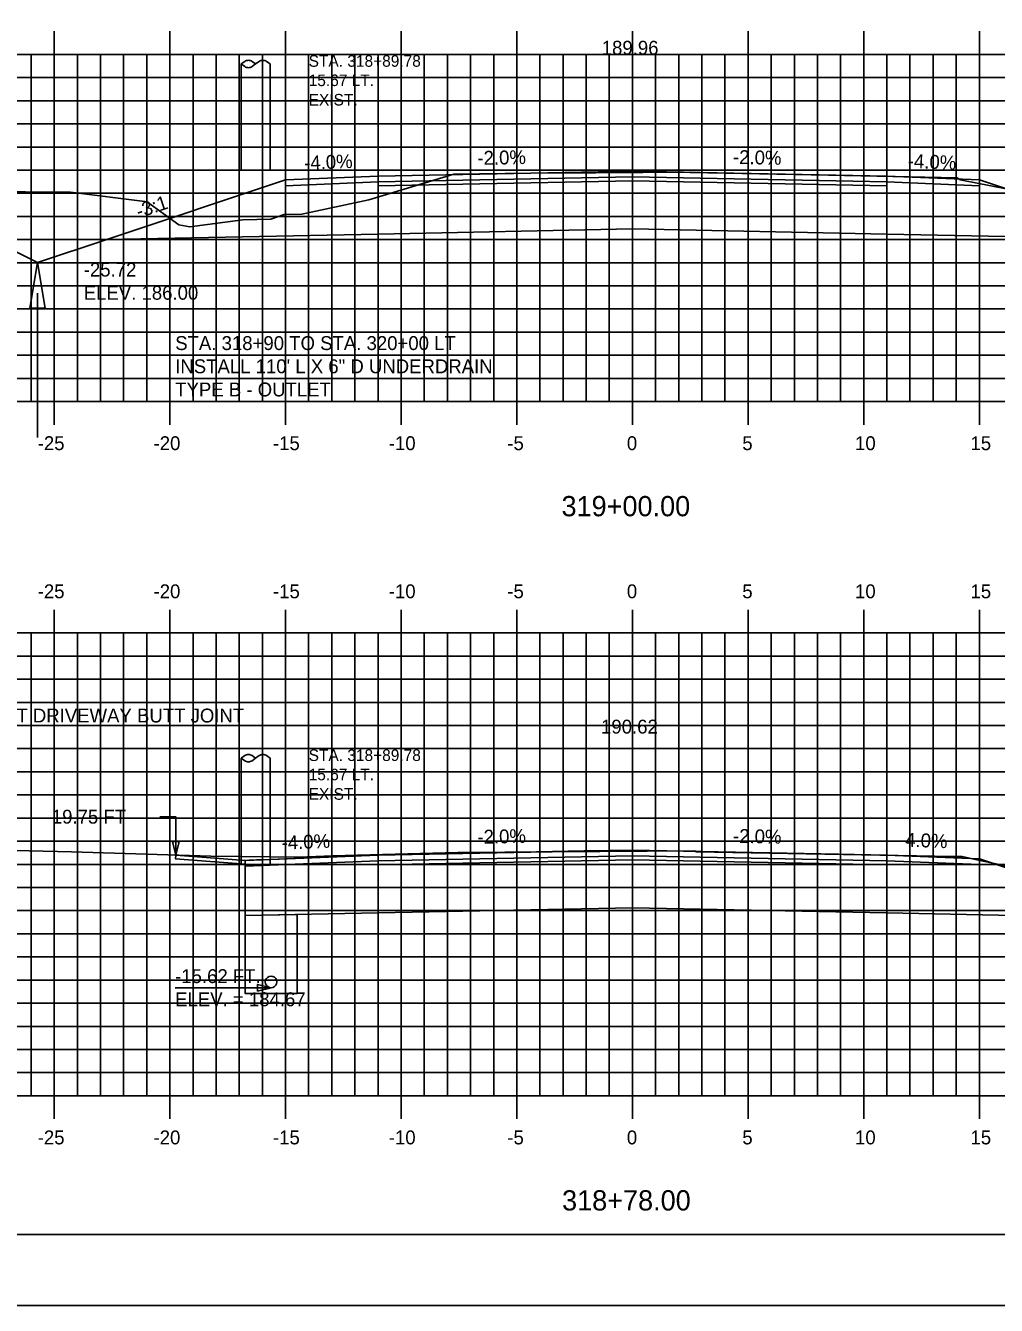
# Model space of a CAD drawing. Extents: x 1139428 to 1139598, y 608981 to 609091.
# Drawn here: x 1139485.2 to 1139527.2, y 608981.3 to 609036.6 of the extents above; entities that cross this region are included whole.
import ezdxf

# ---------------------------------------------------------------- set-up
doc = ezdxf.new("R2010")
doc.units = 0
for name, color, linetype in [('ANNOTATION', 7, 'Continuous'), ('BORDER', 7, 'Continuous'), ('D_Drainage_Ditch_Line', 7, 'Continuous'), ('D_Drainage_Underdrain', 7, 'Continuous'), ('D_Drainage_Underdrain_06in', 7, 'Continuous'), ('D_Roadway_Centerline', 7, 'Continuous'), ('D_Roadway_Centerline_Text', 7, 'Continuous'), ('D_Roadway_Edge_Shoulder', 7, 'Continuous'), ('D_Roadway_Edge_TW', 7, 'Continuous'), ('D_Roadway_Pavement', 7, 'Continuous'), ('D_Roadway_SlopeLines', 7, 'Continuous'), ('D_Roadway_SubGrade', 7, 'Continuous'), ('D_Text_Monospaced', 7, 'Continuous'), ('D_Text_Standard', 7, 'Continuous'), ('H_V ANNOTATION', 7, 'Continuous'), ('MAJOR', 7, 'Continuous'), ('MINOR', 7, 'Continuous'), ('PLOT BOUNDARY', 7, 'Continuous'), ('S_Roadway_Centerline', 7, 'Continuous'), ('S_Utilities_Pole_Stub', 7, 'Continuous')]:
    doc.layers.add(name, color=color, linetype=linetype)

msp = doc.modelspace()

# ---------------------------------------------------------------- linework, layer by layer
for points in [[(1139477.03, 609029.476), (1139478.28, 609029.383), (1139479.53, 609029.138), (1139480.78, 609028.741), (1139482.03, 609028.192), (1139485.737, 609026.338), (1139488.737, 609027.338), (1139496.461, 609029.913), (1139496.462, 609029.913), (1139500.462, 609030.073), (1139511.462, 609030.293), (1139522.462, 609030.073), (1139526.462, 609029.913), (1139534.185, 609027.338), (1139537.185, 609026.338), (1139537.772, 609026.632), (1139539.022, 609027.171), (1139540.272, 609027.537), (1139541.522, 609027.732), (1139542.772, 609027.754)], [(1139494.711, 609000.505), (1139494.712, 609000.505), (1139494.712, 609000.505), (1139494.878, 609000.511), (1139494.916, 609000.513), (1139494.972, 609000.515), (1139495.212, 609000.525), (1139495.414, 609000.533), (1139495.462, 609000.535), (1139499.514, 609000.697), (1139500.462, 609000.735), (1139509.376, 609000.913), (1139511.462, 609000.955), (1139520.376, 609000.776), (1139522.462, 609000.735), (1139525.703, 609000.605), (1139526.462, 609000.575), (1139532.721, 608998.488)]]:
    msp.add_lwpolyline(points)
at = {"layer": 'BORDER'}
msp.add_lwpolyline([(1139436.462, 608984.335), (1139596.462, 608984.335), (1139596.462, 609089.335), (1139436.462, 609089.335)], close=True, dxfattribs=at)
at = {"layer": 'D_Drainage_Ditch_Line'}
msp.add_line((1139485.737, 609025.026), (1139485.737, 609018.783), dxfattribs=at)
msp.add_lwpolyline([(1139486.065, 609024.37), (1139485.409, 609024.37), (1139485.737, 609026.338)], close=True, dxfattribs=at)
at = {"layer": 'D_Drainage_Underdrain'}
msp.add_lwpolyline([(1139494.712, 608998.12), (1139494.712, 608994.755), (1139496.962, 608994.755), (1139496.962, 608998.165)], close=True, dxfattribs=at)
at = {"layer": 'D_Drainage_Underdrain_06in'}
msp.add_lwpolyline([(1139495.837, 608995.505), (1139495.915, 608995.492), (1139495.984, 608995.457), (1139496.04, 608995.402), (1139496.075, 608995.332), (1139496.087, 608995.255), (1139496.075, 608995.177), (1139496.04, 608995.108), (1139495.984, 608995.052), (1139495.915, 608995.017), (1139495.837, 608995.005), (1139495.76, 608995.017), (1139495.69, 608995.052), (1139495.635, 608995.108), (1139495.6, 608995.177), (1139495.587, 608995.255), (1139495.6, 608995.332), (1139495.635, 608995.402), (1139495.69, 608995.457), (1139495.76, 608995.492)], close=True, dxfattribs=at)
at = {"layer": 'D_Roadway_Edge_Shoulder'}
for points in [[(1139500.462, 609030.073), (1139496.462, 609029.913), (1139496.462, 609029.663), (1139500.462, 609029.823)], [(1139522.462, 609030.073), (1139526.462, 609029.913), (1139526.462, 609029.663), (1139522.462, 609029.823)], [(1139494.712, 609000.505), (1139491.716, 609000.734), (1139491.708, 609000.568), (1139494.711, 609000.338)], [(1139522.462, 609000.735), (1139526.462, 609000.575), (1139526.462, 609000.325), (1139522.462, 609000.485)]]:
    msp.add_lwpolyline(points, close=True, dxfattribs=at)
msp.add_lwpolyline([(1139500.462, 609000.735), (1139495.462, 609000.535), (1139494.712, 609000.505), (1139494.712, 609000.255), (1139500.462, 609000.485), (1139500.462, 609000.735)], dxfattribs=at)
at = {"layer": 'D_Roadway_Edge_TW'}
for points in [[(1139500.462, 609029.823), (1139500.462, 609030.073), (1139511.462, 609030.293), (1139522.462, 609030.073), (1139522.462, 609029.823), (1139511.462, 609030.043)], [(1139500.462, 609000.485), (1139500.462, 609000.735), (1139511.462, 609000.955), (1139522.462, 609000.735), (1139522.462, 609000.485), (1139511.462, 609000.705)]]:
    msp.add_lwpolyline(points, close=True, dxfattribs=at)
at = {"layer": 'D_Roadway_Pavement'}
for points in [[(1139500.462, 609029.656), (1139500.462, 609029.823), (1139511.462, 609030.043), (1139522.462, 609029.823), (1139522.462, 609029.656), (1139511.462, 609029.876)], [(1139500.462, 609000.318), (1139500.462, 609000.485), (1139511.462, 609000.705), (1139522.462, 609000.485), (1139522.462, 609000.318), (1139511.462, 609000.538)]]:
    msp.add_lwpolyline(points, close=True, dxfattribs=at)
at = {"layer": 'D_Roadway_SlopeLines'}
for points in [[(1139485.737, 609026.338), (1139482.03, 609028.192), (1139480.78, 609028.741), (1139479.53, 609029.138), (1139478.28, 609029.383), (1139477.03, 609029.476)], [(1139488.737, 609027.338), (1139485.737, 609026.338)]]:
    msp.add_lwpolyline(points, dxfattribs=at)
at = {"layer": 'D_Roadway_SubGrade'}
for points in [[(1139500.462, 609029.656), (1139500.462, 609029.823), (1139496.462, 609029.663), (1139496.462, 609029.913), (1139496.461, 609029.913), (1139488.737, 609027.338), (1139500.462, 609027.573)], [(1139500.462, 609027.573), (1139500.462, 609029.656), (1139511.462, 609029.876), (1139522.462, 609029.656), (1139522.462, 609027.573), (1139511.462, 609027.793)], [(1139522.462, 609029.656), (1139522.462, 609029.823), (1139526.462, 609029.663), (1139526.462, 609029.913), (1139526.462, 609029.913), (1139534.185, 609027.338), (1139522.462, 609027.573)], [(1139494.711, 608999.505), (1139494.712, 608998.12), (1139500.462, 608998.235), (1139500.462, 609000.318), (1139500.462, 609000.485), (1139494.712, 609000.255), (1139494.712, 609000.505), (1139494.711, 609000.505)], [(1139500.462, 609000.318), (1139500.462, 609000.485), (1139494.712, 609000.255), (1139494.712, 609000.505), (1139494.711, 609000.505), (1139494.712, 608998.12), (1139500.462, 608998.235)], [(1139500.462, 608998.235), (1139500.462, 609000.318), (1139511.462, 609000.538), (1139522.462, 609000.318), (1139522.462, 608998.235), (1139511.462, 608998.455)], [(1139522.462, 609000.318), (1139522.462, 609000.485), (1139526.462, 609000.325), (1139526.462, 609000.575), (1139526.462, 609000.575), (1139534.185, 608998), (1139522.462, 608998.235)]]:
    msp.add_lwpolyline(points, close=True, dxfattribs=at)
at = {"layer": 'D_Text_Standard'}
msp.add_line((1139491.688, 608995.005), (1139494.155, 608995.005), dxfattribs=at)
for points in [[(1139491.716, 609000.734), (1139491.712, 609002.396), (1139491.032, 609002.396)], [(1139495.837, 608995.005), (1139494.835, 608995.005), (1139494.155, 608995.005)]]:
    msp.add_lwpolyline(points, dxfattribs=at)
for points in [[(1139491.716, 609000.734), (1139491.569, 609001.316), (1139491.86, 609001.316)], [(1139495.837, 608995.005), (1139495.255, 608994.859), (1139495.255, 608995.15)]]:
    msp.add_lwpolyline(points, close=True, dxfattribs=at)
at = {"layer": 'MAJOR'}
for p, q in [((1139486.462, 609036.337), (1139486.462, 609035.335)), ((1139491.462, 609036.337), (1139491.462, 609035.335)), ((1139496.462, 609036.337), (1139496.462, 609035.335)), ((1139501.462, 609036.337), (1139501.462, 609035.335)), ((1139506.462, 609036.337), (1139506.462, 609035.335)), ((1139511.462, 609036.337), (1139511.462, 609035.335)), ((1139516.462, 609036.337), (1139516.462, 609035.335)), ((1139521.462, 609036.337), (1139521.462, 609035.335)), ((1139526.462, 609036.337), (1139526.462, 609035.335)), ((1139441.462, 609035.335), (1139581.462, 609035.335)), ((1139441.462, 609035.335), (1139581.462, 609035.335)), ((1139486.462, 609020.335), (1139486.462, 609035.335)), ((1139491.462, 609020.335), (1139491.462, 609035.335)), ((1139496.462, 609020.335), (1139496.462, 609035.335)), ((1139501.462, 609020.335), (1139501.462, 609035.335)), ((1139506.462, 609020.335), (1139506.462, 609035.335)), ((1139511.462, 609020.335), (1139511.462, 609035.335)), ((1139516.462, 609020.335), (1139516.462, 609035.335)), ((1139521.462, 609020.335), (1139521.462, 609035.335)), ((1139526.462, 609020.335), (1139526.462, 609035.335)), ((1139441.462, 609030.335), (1139581.462, 609030.335)), ((1139441.462, 609025.335), (1139581.462, 609025.335)), ((1139441.462, 609020.335), (1139581.462, 609020.335)), ((1139441.462, 609020.335), (1139581.462, 609020.335)), ((1139486.462, 609019.333), (1139486.462, 609020.335)), ((1139491.462, 609019.333), (1139491.462, 609020.335)), ((1139496.462, 609019.333), (1139496.462, 609020.335)), ((1139501.462, 609019.333), (1139501.462, 609020.335)), ((1139506.462, 609019.333), (1139506.462, 609020.335)), ((1139511.462, 609019.333), (1139511.462, 609020.335)), ((1139516.462, 609019.333), (1139516.462, 609020.335)), ((1139521.462, 609019.333), (1139521.462, 609020.335)), ((1139526.462, 609019.333), (1139526.462, 609020.335)), ((1139486.462, 609011.337), (1139486.462, 609010.335)), ((1139491.462, 609011.337), (1139491.462, 609010.335)), ((1139496.462, 609011.337), (1139496.462, 609010.335)), ((1139501.462, 609011.337), (1139501.462, 609010.335)), ((1139506.462, 609011.337), (1139506.462, 609010.335)), ((1139511.462, 609011.337), (1139511.462, 609010.335)), ((1139516.462, 609011.337), (1139516.462, 609010.335)), ((1139521.462, 609011.337), (1139521.462, 609010.335)), ((1139526.462, 609011.337), (1139526.462, 609010.335)), ((1139441.462, 609010.335), (1139581.462, 609010.335)), ((1139441.462, 609010.335), (1139581.462, 609010.335)), ((1139486.462, 608990.335), (1139486.462, 609010.335)), ((1139491.462, 608990.335), (1139491.462, 609010.335)), ((1139496.462, 608990.335), (1139496.462, 609010.335)), ((1139501.462, 608990.335), (1139501.462, 609010.335)), ((1139506.462, 608990.335), (1139506.462, 609010.335)), ((1139511.462, 608990.335), (1139511.462, 609010.335)), ((1139516.462, 608990.335), (1139516.462, 609010.335)), ((1139521.462, 608990.335), (1139521.462, 609010.335)), ((1139526.462, 608990.335), (1139526.462, 609010.335)), ((1139441.462, 609005.335), (1139581.462, 609005.335)), ((1139441.462, 609000.335), (1139581.462, 609000.335)), ((1139441.462, 608995.335), (1139581.462, 608995.335)), ((1139441.462, 608990.335), (1139581.462, 608990.335)), ((1139441.462, 608990.335), (1139581.462, 608990.335)), ((1139486.462, 608989.333), (1139486.462, 608990.335)), ((1139491.462, 608989.333), (1139491.462, 608990.335)), ((1139496.462, 608989.333), (1139496.462, 608990.335)), ((1139501.462, 608989.333), (1139501.462, 608990.335)), ((1139506.462, 608989.333), (1139506.462, 608990.335)), ((1139511.462, 608989.333), (1139511.462, 608990.335)), ((1139516.462, 608989.333), (1139516.462, 608990.335)), ((1139521.462, 608989.333), (1139521.462, 608990.335)), ((1139526.462, 608989.333), (1139526.462, 608990.335))]:
    msp.add_line(p, q, dxfattribs=at)
at = {"layer": 'MINOR'}
for p, q in [((1139485.462, 609020.335), (1139485.462, 609035.335)), ((1139487.462, 609020.335), (1139487.462, 609035.335)), ((1139488.462, 609020.335), (1139488.462, 609035.335)), ((1139489.462, 609020.335), (1139489.462, 609035.335)), ((1139490.462, 609020.335), (1139490.462, 609035.335)), ((1139492.462, 609020.335), (1139492.462, 609035.335)), ((1139493.462, 609020.335), (1139493.462, 609035.335)), ((1139494.462, 609020.335), (1139494.462, 609035.335)), ((1139495.462, 609020.335), (1139495.462, 609035.335)), ((1139497.462, 609020.335), (1139497.462, 609035.335)), ((1139498.462, 609020.335), (1139498.462, 609035.335)), ((1139499.462, 609020.335), (1139499.462, 609035.335)), ((1139500.462, 609020.335), (1139500.462, 609035.335)), ((1139502.462, 609020.335), (1139502.462, 609035.335)), ((1139503.462, 609020.335), (1139503.462, 609035.335)), ((1139504.462, 609020.335), (1139504.462, 609035.335)), ((1139505.462, 609020.335), (1139505.462, 609035.335)), ((1139507.462, 609020.335), (1139507.462, 609035.335)), ((1139508.462, 609020.335), (1139508.462, 609035.335)), ((1139509.462, 609020.335), (1139509.462, 609035.335)), ((1139510.462, 609020.335), (1139510.462, 609035.335)), ((1139512.462, 609020.335), (1139512.462, 609035.335)), ((1139513.462, 609020.335), (1139513.462, 609035.335)), ((1139514.462, 609020.335), (1139514.462, 609035.335)), ((1139515.462, 609020.335), (1139515.462, 609035.335)), ((1139517.462, 609020.335), (1139517.462, 609035.335)), ((1139518.462, 609020.335), (1139518.462, 609035.335)), ((1139519.462, 609020.335), (1139519.462, 609035.335)), ((1139520.462, 609020.335), (1139520.462, 609035.335)), ((1139522.462, 609020.335), (1139522.462, 609035.335)), ((1139523.462, 609020.335), (1139523.462, 609035.335)), ((1139524.462, 609020.335), (1139524.462, 609035.335)), ((1139525.462, 609020.335), (1139525.462, 609035.335)), ((1139441.462, 609034.335), (1139581.462, 609034.335)), ((1139441.462, 609033.335), (1139581.462, 609033.335)), ((1139441.462, 609032.335), (1139581.462, 609032.335)), ((1139441.462, 609031.335), (1139581.462, 609031.335)), ((1139441.462, 609029.335), (1139581.462, 609029.335)), ((1139441.462, 609028.335), (1139581.462, 609028.335)), ((1139441.462, 609027.335), (1139581.462, 609027.335)), ((1139441.462, 609026.335), (1139581.462, 609026.335)), ((1139441.462, 609024.335), (1139581.462, 609024.335)), ((1139441.462, 609023.335), (1139581.462, 609023.335)), ((1139441.462, 609022.335), (1139581.462, 609022.335)), ((1139441.462, 609021.335), (1139581.462, 609021.335)), ((1139485.462, 608990.335), (1139485.462, 609010.335)), ((1139487.462, 608990.335), (1139487.462, 609010.335)), ((1139488.462, 608990.335), (1139488.462, 609010.335)), ((1139489.462, 608990.335), (1139489.462, 609010.335)), ((1139490.462, 608990.335), (1139490.462, 609010.335)), ((1139492.462, 608990.335), (1139492.462, 609010.335)), ((1139493.462, 608990.335), (1139493.462, 609010.335)), ((1139494.462, 608990.335), (1139494.462, 609010.335)), ((1139495.462, 608990.335), (1139495.462, 609010.335)), ((1139497.462, 608990.335), (1139497.462, 609010.335)), ((1139498.462, 608990.335), (1139498.462, 609010.335)), ((1139499.462, 608990.335), (1139499.462, 609010.335)), ((1139500.462, 608990.335), (1139500.462, 609010.335)), ((1139502.462, 608990.335), (1139502.462, 609010.335)), ((1139503.462, 608990.335), (1139503.462, 609010.335)), ((1139504.462, 608990.335), (1139504.462, 609010.335)), ((1139505.462, 608990.335), (1139505.462, 609010.335)), ((1139507.462, 608990.335), (1139507.462, 609010.335)), ((1139508.462, 608990.335), (1139508.462, 609010.335)), ((1139509.462, 608990.335), (1139509.462, 609010.335)), ((1139510.462, 608990.335), (1139510.462, 609010.335)), ((1139512.462, 608990.335), (1139512.462, 609010.335)), ((1139513.462, 608990.335), (1139513.462, 609010.335)), ((1139514.462, 608990.335), (1139514.462, 609010.335)), ((1139515.462, 608990.335), (1139515.462, 609010.335)), ((1139517.462, 608990.335), (1139517.462, 609010.335)), ((1139518.462, 608990.335), (1139518.462, 609010.335)), ((1139519.462, 608990.335), (1139519.462, 609010.335)), ((1139520.462, 608990.335), (1139520.462, 609010.335)), ((1139522.462, 608990.335), (1139522.462, 609010.335)), ((1139523.462, 608990.335), (1139523.462, 609010.335)), ((1139524.462, 608990.335), (1139524.462, 609010.335)), ((1139525.462, 608990.335), (1139525.462, 609010.335)), ((1139441.462, 609009.335), (1139581.462, 609009.335)), ((1139441.462, 609008.335), (1139581.462, 609008.335)), ((1139441.462, 609007.335), (1139581.462, 609007.335)), ((1139441.462, 609006.335), (1139581.462, 609006.335)), ((1139441.462, 609004.335), (1139581.462, 609004.335)), ((1139441.462, 609003.335), (1139581.462, 609003.335)), ((1139441.462, 609002.335), (1139581.462, 609002.335)), ((1139441.462, 609001.335), (1139581.462, 609001.335)), ((1139441.462, 608999.335), (1139581.462, 608999.335)), ((1139441.462, 608998.335), (1139581.462, 608998.335)), ((1139441.462, 608997.335), (1139581.462, 608997.335)), ((1139441.462, 608996.335), (1139581.462, 608996.335)), ((1139441.462, 608994.335), (1139581.462, 608994.335)), ((1139441.462, 608993.335), (1139581.462, 608993.335)), ((1139441.462, 608992.335), (1139581.462, 608992.335)), ((1139441.462, 608991.335), (1139581.462, 608991.335))]:
    msp.add_line(p, q, dxfattribs=at)
at = {"layer": 'PLOT BOUNDARY'}
msp.add_lwpolyline([(1139428.369, 608981.276), (1139598.369, 608981.276), (1139598.369, 609091.276), (1139428.369, 609091.276)], close=True, dxfattribs=at)
at = {"layer": 'S_Roadway_Centerline'}
for points in [[(1139477.443, 609029.46), (1139487.16, 609029.377), (1139490.376, 609028.984), (1139490.495, 609028.954), (1139491.849, 609027.973), (1139492.322, 609027.889), (1139494.615, 609028.187), (1139495.827, 609028.221), (1139496.404, 609028.415), (1139497.161, 609028.43), (1139500.06, 609029.05), (1139503.737, 609030.165), (1139507.074, 609030.209), (1139509.874, 609030.218), (1139513.94, 609030.245), (1139513.977, 609030.228), (1139519.936, 609030.115), (1139525.506, 609029.999), (1139525.637, 609029.92), (1139532.992, 609028.469)], [(1139480.496, 609001.039), (1139487.202, 609000.883), (1139493.235, 609000.684), (1139497.031, 609000.642), (1139498.486, 609000.702), (1139503.916, 609000.851), (1139505.938, 609000.858), (1139514.154, 609000.913), (1139514.219, 609000.883), (1139525.323, 609000.671), (1139525.716, 609000.668), (1139526.352, 609000.532), (1139530.633, 608999.643), (1139534.754, 608998.925), (1139536.789, 608998.821), (1139539.975, 608998.696), (1139564.007, 608998.467), (1139581.462, 608998.619)]]:
    msp.add_lwpolyline(points, dxfattribs=at)
at = {"layer": 'S_Utilities_Pole_Stub'}
for p, q in [((1139494.545, 609034.923), (1139494.701, 609035.033)), ((1139494.545, 609030.303), (1139494.548, 609034.923)), ((1139494.701, 609034.812), (1139494.545, 609034.923)), ((1139495.014, 609035.033), (1139495.17, 609034.923)), ((1139495.17, 609034.923), (1139495.014, 609034.812)), ((1139495.327, 609035.033), (1139495.17, 609034.923)), ((1139495.795, 609034.923), (1139495.639, 609035.033)), ((1139495.795, 609030.303), (1139495.798, 609034.923)), ((1139494.545, 609004.923), (1139494.701, 609005.033)), ((1139494.545, 609000.303), (1139494.548, 609004.923)), ((1139494.701, 609004.812), (1139494.545, 609004.923)), ((1139495.014, 609005.033), (1139495.17, 609004.923)), ((1139495.17, 609004.923), (1139495.014, 609004.812)), ((1139495.327, 609005.033), (1139495.17, 609004.923)), ((1139495.795, 609004.923), (1139495.639, 609005.033)), ((1139495.795, 609000.303), (1139495.798, 609004.923))]:
    msp.add_line(p, q, dxfattribs=at)
for centre, start, end in [((1139494.858, 609034.812), 90, 125.2644), ((1139494.858, 609034.812), 54.7356, 90), ((1139495.483, 609034.812), 90, 125.2644), ((1139495.483, 609034.812), 54.7356, 90), ((1139494.858, 609035.033), 234.7356, 270), ((1139494.858, 609035.033), 270, 305.2644), ((1139494.858, 609004.812), 90, 125.2644), ((1139494.858, 609005.033), 234.7356, 270), ((1139494.858, 609004.812), 54.7356, 90), ((1139494.858, 609005.033), 270, 305.2644), ((1139495.483, 609004.812), 90, 125.2644), ((1139495.483, 609004.812), 54.7356, 90)]:
    msp.add_arc(centre, 0.271, start, end, dxfattribs=at)

# ---------------------------------------------------------------- texts
at = {"layer": 'ANNOTATION'}
for s, rotation, p in [('-2.0%', 1.1458, (1139504.765, 609030.559)), ('-2.0%', 358.8542, (1139515.805, 609030.606)), ('-4.0%', 2.2906, (1139497.278, 609030.346)), ('-4.0%', 357.7094, (1139523.358, 609030.438)), ('-3:1', 18.4348, (1139490.116, 609028.252)), ('-2.0%', 1.1458, (1139504.765, 609001.221)), ('-2.0%', 358.8542, (1139515.805, 609001.268)), ('-4.0%', 2.2906, (1139496.304, 609000.969)), ('-4.0%', 357.7094, (1139522.978, 609001.115))]:
    msp.add_text(s, height=0.6, rotation=rotation, dxfattribs=at).set_placement(p)
for s, p in [('STA. 318+90 TO STA. 320+00 LT', (1139491.692, 609022.561)), ('INSTALL 110\' L X 6" D UNDERDRAIN', (1139491.692, 609021.559)), ('TYPE B - OUTLET', (1139491.692, 609020.557)), ('CONSTRUCT DRIVEWAY BUTT JOINT', (1139480.278, 609006.466))]:
    msp.add_text(s, height=0.6, dxfattribs=at).set_placement(p)
at = {"layer": 'D_Roadway_Centerline'}
for s, p in [('C', (1139511.457, 609030.293)), ('L', (1139511.462, 609030.286)), ('C', (1139511.457, 609000.955)), ('L', (1139511.462, 609000.947))]:
    msp.add_text(s, height=0.0146, dxfattribs=at).set_placement(p)
at = {"layer": 'D_Roadway_Centerline_Text'}
for s, p in [('189.96', (1139510.135, 609035.325)), ('190.62', (1139510.105, 609005.987))]:
    msp.add_text(s, height=0.6, dxfattribs=at).set_placement(p)
at = {"layer": 'D_Text_Monospaced'}
for s, height, p in [('STA. 318+89.78', 0.49998, (1139497.462, 609034.802)), ('15.67 LT.', 0.5, (1139497.462, 609033.968)), ('EXIST. ', 0.5, (1139497.462, 609033.128)), ('STA. 318+89.78', 0.49998, (1139497.462, 609004.802)), ('15.67 LT.', 0.5, (1139497.462, 609003.968)), ('EXIST. ', 0.5, (1139497.462, 609003.128))]:
    msp.add_text(s, height=height, dxfattribs=at).set_placement(p)
at = {"layer": 'D_Text_Standard'}
for s, p in [('-25.72', (1139487.737, 609025.738)), ('ELEV. 186.00', (1139487.737, 609024.736)), ('-19.75 FT', (1139486.09, 609002.096)), ('-15.62 FT.', (1139491.688, 608995.205)), ('ELEV. = 184.67', (1139491.688, 608994.205))]:
    msp.add_text(s, height=0.6, dxfattribs=at).set_placement(p)
at = {"layer": 'H_V ANNOTATION'}
for s, height, p in [('-25', 0.6, (1139485.747, 609018.235)), ('-20', 0.6, (1139490.755, 609018.235)), ('-15', 0.6, (1139495.919, 609018.235)), ('-10', 0.6, (1139500.927, 609018.235)), ('-5', 0.6, (1139506.052, 609018.235)), ('0', 0.6, (1139511.221, 609018.235)), ('5', 0.6, (1139516.213, 609018.235)), ('10', 0.6, (1139521.087, 609018.235)), ('15', 0.6, (1139526.079, 609018.235)), ('319+00.00', 0.875, (1139508.395, 609015.378)), ('-25', 0.6, (1139485.747, 609011.835)), ('-20', 0.6, (1139490.755, 609011.835)), ('-15', 0.6, (1139495.919, 609011.835)), ('-10', 0.6, (1139500.927, 609011.835)), ('-5', 0.6, (1139506.052, 609011.835)), ('0', 0.6, (1139511.221, 609011.835)), ('5', 0.6, (1139516.213, 609011.835)), ('10', 0.6, (1139521.087, 609011.835)), ('15', 0.6, (1139526.079, 609011.835)), ('-25', 0.6, (1139485.747, 608988.235)), ('-20', 0.6, (1139490.755, 608988.235)), ('-15', 0.6, (1139495.919, 608988.235)), ('-10', 0.6, (1139500.927, 608988.235)), ('-5', 0.6, (1139506.052, 608988.235)), ('0', 0.6, (1139511.221, 608988.235)), ('5', 0.6, (1139516.213, 608988.235)), ('10', 0.6, (1139521.087, 608988.235)), ('15', 0.6, (1139526.079, 608988.235)), ('318+78.00', 0.875, (1139508.419, 608985.378))]:
    msp.add_text(s, height=height, dxfattribs=at).set_placement(p)
at = {"layer": 'S_Roadway_Centerline'}
for s, p in [('C', (1139513.934, 609030.245)), ('L', (1139513.94, 609030.238)), ('C', (1139513.971, 609030.22)), ('L', (1139513.977, 609030.213)), ('C', (1139514.149, 609000.913)), ('L', (1139514.154, 609000.906))]:
    msp.add_text(s, height=0.0146, dxfattribs=at).set_placement(p)

doc.saveas('drawing.dxf')
